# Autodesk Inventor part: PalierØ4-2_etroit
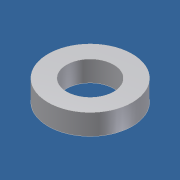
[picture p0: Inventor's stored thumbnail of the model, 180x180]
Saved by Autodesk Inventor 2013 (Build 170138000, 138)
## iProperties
Created: 2011-07
Part Number: PalierØ4-2_etroit
Document SubType Name: Modeling
Designer: domi
Density: 1 g/cm^3
Material: Générique
Author: domi
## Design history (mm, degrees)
sketch "Esquisse1"
  geometry: C1 r 2.1 at (0, 0); C2 r 3.75 at (0, 0); 1 further point
  constraints: 2 centre point, 2 coincident
  dimensions: "d0" = 7.5 diameter of C2; "d1" = 4.2 diameter of C1
extrude "Pallier" new body sketch "Esquisse1" distance "d2" = 1.85; taper "d3" = 0 deg
node "Solide1"
node "Corps solides"
node "Corps surfaciques"
